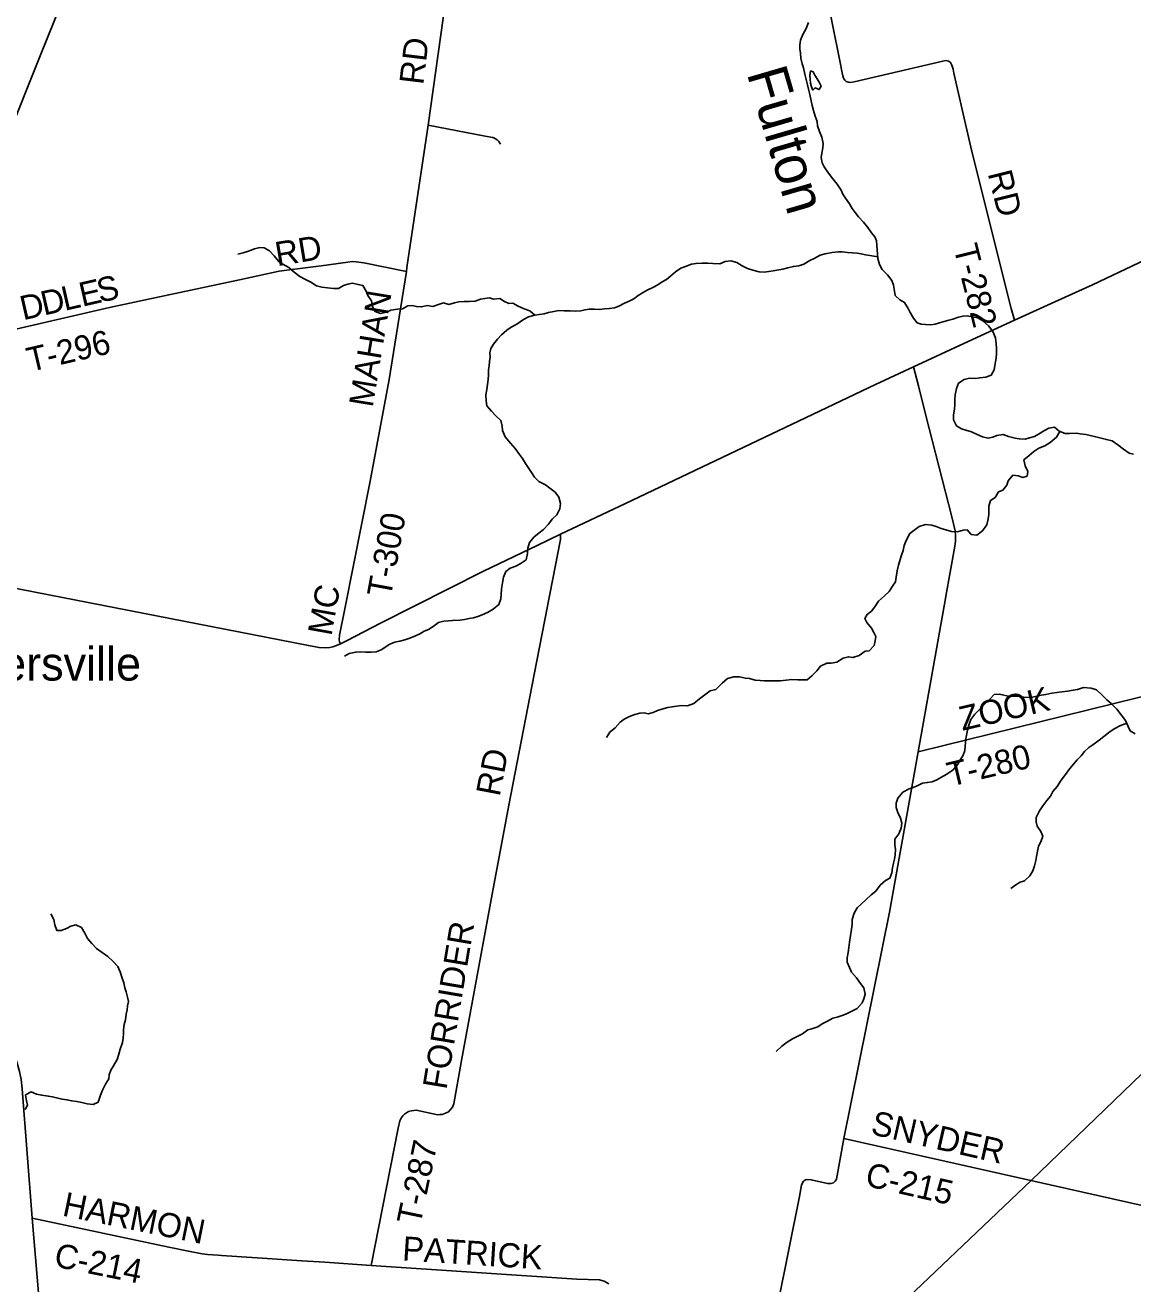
# Model space of a CAD drawing. Extents: x 0 to 34, y 0 to 22.
# Drawn here: x 6.445 to 7.746, y 17.405 to 18.883 of the extents above; entities that cross this region are included whole.
import ezdxf

# ---------------------------------------------------------------- set-up
doc = ezdxf.new("R2010")
doc.units = 0
for name, color, linetype in [('GM_X_County_Road', 7, 'Continuous'), ('GM_X_County_Road_Text', 7, 'Continuous'), ('GM_X_Minor_Lake', 7, 'Continuous'), ('GM_X_Minor_River', 7, 'Continuous'), ('GM_X_Minor_River_Text', 7, 'Continuous'), ('GM_X_Rail_Line', 7, 'Continuous'), ('GM_X_State_Route', 7, 'Continuous'), ('GM_X_Township_Road', 7, 'Continuous'), ('GM_X_Township_Road_Text', 7, 'Continuous'), ('GM_X_Unincorporated_Text', 7, 'Continuous')]:
    doc.layers.add(name, color=color, linetype=linetype)

msp = doc.modelspace()

# ---------------------------------------------------------------- linework, layer by layer
at = {"layer": 'GM_X_County_Road'}
msp.add_line((7.4066, 17.5758), (8.0124, 17.4394), dxfattribs=at)
for points in [[(6.3004, 18.376), (6.3047, 18.3928), (6.3073, 18.4041), (6.3232, 18.4893), (6.3256, 18.5003), (6.3282, 18.5101), (6.3329, 18.523), (6.3382, 18.5363), (6.4625, 18.8471), (6.5726, 19.1199), (6.732, 19.5215), (6.7919, 19.6658)], [(7.5259, 18.21), (7.5264, 18.2125), (7.5366, 18.269), (7.5376, 18.2768), (7.5377, 18.2838), (7.5373, 18.2894), (7.5333, 18.3058), (7.5028, 18.4249), (7.4943, 18.4595), (7.4881, 18.4821)], [(7.4066, 17.5758), (7.4599, 17.8414), (7.4939, 18.0298), (7.5259, 18.21)], [(7.3569, 17.5211), (7.3574, 17.523), (7.3592, 17.5255), (7.3614, 17.5271), (7.3639, 17.5277), (7.3682, 17.5273), (7.3872, 17.523), (7.3913, 17.5228), (7.3942, 17.5237), (7.3963, 17.5257), (7.3979, 17.5281), (7.4066, 17.5758)], [(7.3163, 17.3189), (7.3542, 17.5075), (7.3564, 17.5188), (7.3569, 17.5211)], [(6.4533, 17.4821), (6.6137, 17.4482), (6.6368, 17.4433), (6.6529, 17.4403), (6.6591, 17.4397), (6.6715, 17.4387), (6.6755, 17.4384)], [(6.6755, 17.4384), (6.7176, 17.4356), (6.77, 17.4322), (6.7971, 17.4304), (6.8515, 17.4267), (7.0927, 17.4107), (7.1196, 17.4096), (7.1249, 17.408), (7.1305, 17.405)]]:
    msp.add_lwpolyline(points, dxfattribs=at)
at = {"layer": 'GM_X_Minor_Lake'}
for points in [[(7.3673, 18.8296), (7.3664, 18.8241), (7.3669, 18.8198), (7.3673, 18.815), (7.3686, 18.8107), (7.3701, 18.8069), (7.3729, 18.8097), (7.3775, 18.8076), (7.3788, 18.8098)], [(7.3788, 18.8098), (7.3798, 18.8116), (7.3773, 18.8161), (7.3751, 18.8201), (7.3724, 18.8243), (7.3706, 18.8283), (7.3673, 18.8296)]]:
    msp.add_lwpolyline(points, dxfattribs=at)
at = {"layer": 'GM_X_Minor_River'}
for points in [[(7.3649, 18.8862), (7.3622, 18.8792), (7.3584, 18.8722), (7.3554, 18.8654), (7.3548, 18.8602), (7.3549, 18.8553), (7.3555, 18.8502), (7.356, 18.8445), (7.3577, 18.8378), (7.3592, 18.8329), (7.3607, 18.8255), (7.3622, 18.8194), (7.3637, 18.813), (7.365, 18.808), (7.3667, 18.8016), (7.368, 18.7945), (7.3693, 18.7889), (7.3709, 18.7828), (7.3728, 18.7765), (7.3751, 18.7699), (7.3756, 18.7649), (7.378, 18.7583), (7.3807, 18.7516), (7.382, 18.7444), (7.3819, 18.7391), (7.3808, 18.7328), (7.38, 18.7277), (7.3811, 18.7215), (7.3834, 18.7167), (7.3883, 18.7093), (7.3937, 18.7028), (7.3985, 18.6964), (7.4032, 18.6895), (7.4054, 18.6848), (7.4084, 18.68), (7.4131, 18.6733), (7.4163, 18.6678), (7.4197, 18.6631), (7.4235, 18.6583), (7.4295, 18.652), (7.4348, 18.6456), (7.4391, 18.6393), (7.4427, 18.6345), (7.4448, 18.6298), (7.4451, 18.6243), (7.4455, 18.6195), (7.4461, 18.6142), (7.4464, 18.6091), (7.4485, 18.6021), (7.4515, 18.5964), (7.4577, 18.5899), (7.463, 18.5832), (7.4649, 18.5777), (7.466, 18.5707), (7.4667, 18.5658), (7.4724, 18.5606), (7.4778, 18.5576), (7.482, 18.5503), (7.4842, 18.5456)], [(7.0434, 18.5425), (7.0375, 18.5479), (7.0309, 18.55), (7.024, 18.5531), (7.0179, 18.5567), (7.013, 18.5564), (7.0081, 18.5587), (7.0023, 18.5623), (6.9951, 18.5614), (6.9902, 18.563), (6.9847, 18.5621), (6.9796, 18.5615), (6.9733, 18.5589), (6.9667, 18.5586), (6.9607, 18.5586), (6.9542, 18.5581), (6.9493, 18.557), (6.9425, 18.5553), (6.9363, 18.5571), (6.9304, 18.555), (6.9238, 18.553), (6.917, 18.5538), (6.9105, 18.5523), (6.9045, 18.5527), (6.8994, 18.5539), (6.8943, 18.5536), (6.8882, 18.5502), (6.8822, 18.5495), (6.8746, 18.5484), (6.8695, 18.5463), (6.8623, 18.5445), (6.8559, 18.547), (6.8531, 18.5529), (6.8516, 18.5593), (6.8475, 18.5656), (6.8453, 18.5708), (6.8417, 18.5774), (6.8359, 18.5786), (6.8293, 18.5802), (6.8241, 18.5789), (6.819, 18.5774), (6.8128, 18.574), (6.8071, 18.5739), (6.7999, 18.5748), (6.7933, 18.5757), (6.7871, 18.5772), (6.7803, 18.5814), (6.7741, 18.5847), (6.7677, 18.5881), (6.7609, 18.5933), (6.7545, 18.5987), (6.7477, 18.6025), (6.7428, 18.6056), (6.7376, 18.6124), (6.732, 18.618), (6.7256, 18.6218), (6.7206, 18.6222), (6.7142, 18.6205), (6.7074, 18.6176), (6.7009, 18.6157), (6.6947, 18.6144)], [(7.4463, 18.6111), (7.4371, 18.6127), (7.432, 18.6135), (7.4269, 18.6145), (7.422, 18.6153), (7.4165, 18.6159), (7.4108, 18.6163), (7.4046, 18.6169), (7.3998, 18.6169), (7.3928, 18.6163), (7.3847, 18.6148), (7.3786, 18.6132), (7.3718, 18.6092), (7.3665, 18.6068), (7.3596, 18.6024), (7.3536, 18.6007), (7.3473, 18.5998), (7.3405, 18.5981), (7.3348, 18.5968), (7.33, 18.5959), (7.3236, 18.5948), (7.3185, 18.5941), (7.3128, 18.5933), (7.3069, 18.5934), (7.2997, 18.5955), (7.2935, 18.5974), (7.2871, 18.6006), (7.2806, 18.6045), (7.2736, 18.6064), (7.2672, 18.6055), (7.2609, 18.6031)], [(7.2609, 18.6031), (7.2527, 18.6032), (7.2469, 18.6036), (7.2399, 18.6036), (7.2329, 18.6035), (7.2274, 18.6024), (7.2204, 18.5996), (7.2151, 18.5977), (7.2086, 18.5936), (7.2031, 18.5887), (7.198, 18.5846), (7.1931, 18.5817), (7.1881, 18.5784), (7.1828, 18.5755), (7.1753, 18.5718), (7.1701, 18.5688), (7.165, 18.5658), (7.1597, 18.5617), (7.1544, 18.5589), (7.1487, 18.5566), (7.1421, 18.5533), (7.1371, 18.5514), (7.1313, 18.5505), (7.1252, 18.55), (7.1197, 18.5494), (7.1137, 18.5498), (7.1075, 18.5495), (7.1025, 18.549), (7.0974, 18.5479), (7.0908, 18.5475), (7.0848, 18.5476), (7.0782, 18.5476), (7.0719, 18.548), (7.0657, 18.5469), (7.0598, 18.5456), (7.0547, 18.5443), (7.0487, 18.5436), (7.0435, 18.5425), (7.0362, 18.5405), (7.0301, 18.5375), (7.0223, 18.5322), (7.0157, 18.5287), (7.0107, 18.5251), (7.0043, 18.5197), (6.9999, 18.5144), (6.995, 18.5085), (6.9919, 18.5036), (6.9909, 18.4985), (6.9911, 18.4938), (6.9905, 18.4883), (6.9901, 18.4831), (6.9893, 18.4784), (6.9891, 18.472), (6.9887, 18.467), (6.9881, 18.4612), (6.9871, 18.4555), (6.9859, 18.449), (6.9863, 18.4422), (6.9872, 18.4361), (6.9926, 18.43), (6.9975, 18.4247), (7.0037, 18.419), (7.005, 18.4121), (7.0055, 18.407), (7.0089, 18.3998), (7.0151, 18.3925), (7.0203, 18.3861), (7.0254, 18.3792), (7.0289, 18.3742), (7.0325, 18.3683), (7.0357, 18.3636), (7.0398, 18.3579), (7.043, 18.3523), (7.0482, 18.3472), (7.0562, 18.3432), (7.0611, 18.3395), (7.0674, 18.3347), (7.0719, 18.3288), (7.0738, 18.3216), (7.073, 18.3152), (7.0692, 18.3082), (7.064, 18.3031), (7.0597, 18.2972), (7.0538, 18.2908), (7.0488, 18.2871), (7.0422, 18.2818), (7.0374, 18.2756), (7.0355, 18.2692), (7.0351, 18.2627), (7.0333, 18.2555), (7.0265, 18.2506), (7.0212, 18.2478), (7.0144, 18.2454), (7.0096, 18.2416), (7.0069, 18.2348), (7.0056, 18.2284), (7.0046, 18.2214), (7.0042, 18.2146), (7.0038, 18.2094), (7.0013, 18.2028), (6.9946, 18.1974)], [(7.4842, 18.5456), (7.4884, 18.5391), (7.4925, 18.5336), (7.4974, 18.5319), (7.5024, 18.5315), (7.5088, 18.5313), (7.5139, 18.532), (7.5189, 18.5335), (7.5244, 18.5352), (7.5297, 18.5369), (7.5346, 18.538), (7.541, 18.5402), (7.5465, 18.5415), (7.5513, 18.5419), (7.5575, 18.5407), (7.5638, 18.5394), (7.5698, 18.5361), (7.5764, 18.53), (7.5815, 18.5236), (7.5845, 18.516), (7.5853, 18.5091), (7.5856, 18.504), (7.5856, 18.4981), (7.5854, 18.4922), (7.5838, 18.4837), (7.583, 18.4784), (7.5796, 18.4722), (7.5732, 18.4697), (7.5661, 18.4692), (7.5612, 18.4683), (7.5542, 18.4688), (7.5478, 18.467), (7.5413, 18.4628), (7.5386, 18.4566), (7.5373, 18.449), (7.5369, 18.4435), (7.5368, 18.4372), (7.5365, 18.4325), (7.5351, 18.4251), (7.5351, 18.4198), (7.5386, 18.4126), (7.5445, 18.4091), (7.5498, 18.4074), (7.5564, 18.4055), (7.5632, 18.4026), (7.5693, 18.3996), (7.5759, 18.398), (7.5814, 18.3995), (7.5861, 18.4012), (7.5934, 18.4025), (7.6, 18.4), (7.6075, 18.3981), (7.6125, 18.3975), (7.6195, 18.3969), (7.6244, 18.3984), (7.6303, 18.4002), (7.6352, 18.4027), (7.6421, 18.407), (7.6472, 18.4099), (7.654, 18.4112), (7.6593, 18.4066), (7.6665, 18.4035), (7.6714, 18.4037), (7.6792, 18.404), (7.6841, 18.4031), (7.6905, 18.4023), (7.6956, 18.4013), (7.7023, 18.3996), (7.7087, 18.398), (7.7149, 18.3965), (7.7216, 18.3949), (7.7284, 18.3905), (7.735, 18.3852), (7.7414, 18.3806), (7.7465, 18.3793)], [(7.6602, 18.4062), (7.6562, 18.3994), (7.6488, 18.3932), (7.6424, 18.3892), (7.6353, 18.3866), (7.6296, 18.3824), (7.6241, 18.3777), (7.618, 18.3726), (7.6193, 18.3658), (7.6227, 18.3589), (7.6216, 18.3536), (7.6166, 18.3521), (7.6113, 18.354), (7.6051, 18.3548), (7.5996, 18.348), (7.5979, 18.3431), (7.5933, 18.3371), (7.5882, 18.335), (7.5842, 18.3287), (7.5788, 18.3248), (7.5767, 18.3185), (7.5767, 18.3081), (7.5757, 18.3015), (7.5746, 18.2963), (7.5692, 18.2894), (7.5628, 18.2843), (7.5561, 18.285), (7.5514, 18.2904), (7.5465, 18.2902), (7.5399, 18.2881), (7.533, 18.2884), (7.5264, 18.2905), (7.5209, 18.292), (7.5149, 18.2945), (7.51, 18.2959), (7.5024, 18.2968), (7.495, 18.2944), (7.4887, 18.2897), (7.484, 18.2863), (7.4798, 18.2782), (7.4775, 18.2723), (7.4763, 18.2662), (7.4742, 18.2609), (7.4727, 18.2558), (7.4706, 18.2492), (7.469, 18.2425), (7.4678, 18.2348), (7.4671, 18.2296), (7.4636, 18.2244), (7.4596, 18.2181), (7.4541, 18.213), (7.4473, 18.2066), (7.4427, 18.2002), (7.4389, 18.1949), (7.4338, 18.1913), (7.4313, 18.1864), (7.4333, 18.1816), (7.439, 18.1749), (7.4418, 18.17), (7.4441, 18.1653), (7.4433, 18.1603), (7.442, 18.1546), (7.4364, 18.1486), (7.4317, 18.1482), (7.4245, 18.1431), (7.4169, 18.1405), (7.412, 18.1415), (7.4057, 18.1398), (7.3983, 18.1351), (7.3915, 18.134), (7.3864, 18.134), (7.379, 18.1306), (7.3746, 18.125), (7.3687, 18.1191), (7.3634, 18.1142), (7.3524, 18.1142), (7.3454, 18.1146), (7.3386, 18.1141), (7.3315, 18.1134), (7.3132, 18.1134), (7.3082, 18.1137), (7.3024, 18.1141), (7.2957, 18.116), (7.2908, 18.1162), (7.284, 18.1179), (7.2772, 18.118), (7.2698, 18.1159), (7.2635, 18.1104), (7.256, 18.1031)], [(6.9946, 18.1974), (6.988, 18.1936), (6.9817, 18.1906), (6.9768, 18.1886), (6.9715, 18.1871), (6.9666, 18.1866), (6.9609, 18.1851), (6.9554, 18.1845), (6.9469, 18.184), (6.942, 18.1835), (6.9367, 18.1832), (6.9305, 18.1819), (6.924, 18.1772), (6.9187, 18.1734), (6.9136, 18.1716), (6.9085, 18.1684), (6.9033, 18.1661), (6.8969, 18.1633), (6.891, 18.1615), (6.885, 18.1598), (6.8791, 18.1585), (6.8732, 18.1561), (6.863, 18.1497), (6.8573, 18.1473), (6.8514, 18.1467), (6.8446, 18.147), (6.8388, 18.1474), (6.8333, 18.1469), (6.8255, 18.1454), (6.82, 18.142)], [(7.256, 18.1031), (7.2494, 18.1013), (7.2431, 18.0969), (7.237, 18.0921), (7.2302, 18.0866), (7.223, 18.084), (7.216, 18.0842), (7.2047, 18.0828), (7.1998, 18.0819), (7.1926, 18.08), (7.1876, 18.0783), (7.1825, 18.0759), (7.1768, 18.0746), (7.1719, 18.0756), (7.167, 18.0753), (7.161, 18.0738), (7.1549, 18.0715), (7.1486, 18.0682), (7.1437, 18.0646), (7.1378, 18.0582), (7.1317, 18.0531), (7.1279, 18.0465)], [(7.7486, 18.0508), (7.7429, 18.0544), (7.7405, 18.0595), (7.7371, 18.0667), (7.7322, 18.0732), (7.7269, 18.0801), (7.7203, 18.0867), (7.7154, 18.0909), (7.7096, 18.0968), (7.7032, 18.1025), (7.6969, 18.1046), (7.6878, 18.1053), (7.681, 18.1032), (7.6759, 18.1021), (7.6691, 18.1012), (7.6626, 18.1004), (7.6566, 18.0997), (7.6509, 18.0988), (7.6437, 18.0973), (7.6384, 18.0965), (7.6332, 18.0952), (7.6279, 18.0939), (7.6202, 18.0938), (7.6128, 18.0948), (7.6063, 18.0952), (7.6014, 18.095), (7.5942, 18.0965), (7.5891, 18.0977), (7.5832, 18.097), (7.5779, 18.0915), (7.573, 18.0868), (7.5602, 18.0741), (7.5558, 18.0679), (7.5533, 18.061), (7.5518, 18.0552), (7.5505, 18.0493)], [(7.7387, 18.0634), (7.7305, 18.0605), (7.7246, 18.0573), (7.7191, 18.0539), (7.7118, 18.0477), (7.7063, 18.0437), (7.6989, 18.0381), (7.6942, 18.0349), (7.689, 18.0301), (7.6852, 18.0252), (7.6805, 18.0203), (7.6761, 18.0154), (7.6719, 18.0101), (7.6666, 18.0031), (7.6616, 17.9965), (7.6571, 17.9893), (7.6521, 17.9831), (7.6491, 17.9778), (7.6447, 17.9727), (7.6403, 17.9664), (7.6363, 17.9604), (7.6325, 17.9526), (7.6325, 17.9475), (7.6336, 17.9424), (7.6377, 17.9361), (7.64, 17.9308), (7.6379, 17.9241), (7.6352, 17.9192), (7.6338, 17.9131), (7.6329, 17.9069), (7.6319, 17.9022), (7.6305, 17.8959), (7.6286, 17.89), (7.625, 17.8844), (7.6185, 17.8783), (7.6136, 17.8766), (7.6085, 17.8738), (7.6024, 17.8695)], [(7.5505, 18.0493), (7.5497, 18.0446), (7.5489, 18.0364), (7.5485, 18.0315), (7.5468, 18.0258), (7.5435, 18.0207), (7.5403, 18.0152), (7.5348, 18.0088), (7.5275, 18.0037), (7.5205, 17.9995), (7.5158, 17.9969), (7.5101, 17.9947), (7.5044, 17.9937), (7.4989, 17.9932), (7.4926, 17.9898), (7.4879, 17.9881), (7.483, 17.9862), (7.4759, 17.9823), (7.4697, 17.9753), (7.4679, 17.9696), (7.4681, 17.9645), (7.4698, 17.9584), (7.4732, 17.9521), (7.4747, 17.9459), (7.4737, 17.94), (7.4712, 17.9337), (7.4664, 17.9271), (7.4662, 17.9205), (7.4671, 17.915), (7.4667, 17.9089), (7.466, 17.9038), (7.4648, 17.8991), (7.4638, 17.8937), (7.4629, 17.8877), (7.4604, 17.8814), (7.4554, 17.8786), (7.4492, 17.8733), (7.444, 17.8661), (7.4385, 17.862), (7.4271, 17.8514), (7.4222, 17.8465), (7.4185, 17.8405), (7.4164, 17.8329), (7.4162, 17.827), (7.4149, 17.819), (7.4141, 17.8143), (7.4133, 17.8065), (7.4123, 17.7999), (7.4115, 17.794), (7.4104, 17.7879), (7.4105, 17.783), (7.413, 17.7766), (7.4154, 17.7712), (7.4213, 17.7644), (7.426, 17.7579), (7.4301, 17.7526), (7.4314, 17.7452), (7.4301, 17.7399), (7.4278, 17.735), (7.4221, 17.7283), (7.4168, 17.7255), (7.4095, 17.7223), (7.4044, 17.7201), (7.3985, 17.7184), (7.3934, 17.7169), (7.3866, 17.7133), (7.3811, 17.7105), (7.3758, 17.7069), (7.3689, 17.7045), (7.3642, 17.7035), (7.3579, 17.6988), (7.3524, 17.696), (7.3462, 17.6928), (7.3399, 17.6887), (7.3336, 17.6841), (7.3268, 17.6781)], [(6.4449, 17.6098), (6.4478, 17.6149), (6.4467, 17.6198), (6.4454, 17.6269), (6.4519, 17.6304), (6.4581, 17.6279), (6.4645, 17.6265), (6.4721, 17.6255), (6.4772, 17.6246), (6.4834, 17.6232), (6.4883, 17.6218), (6.494, 17.6212), (6.4996, 17.6199), (6.5055, 17.6191), (6.5117, 17.6179), (6.5177, 17.6165), (6.5249, 17.6155), (6.5306, 17.6183), (6.5333, 17.6265), (6.536, 17.6325), (6.5394, 17.6397), (6.5431, 17.6457), (6.5438, 17.6507), (6.5456, 17.6558), (6.5486, 17.6611), (6.553, 17.6684), (6.5549, 17.6749), (6.5565, 17.6807), (6.5594, 17.6885), (6.5602, 17.6934), (6.5606, 17.6989), (6.5604, 17.7036), (6.5612, 17.7095), (6.5627, 17.7152), (6.5637, 17.7216), (6.5647, 17.7268), (6.5653, 17.7317), (6.5665, 17.7368), (6.5652, 17.7419), (6.5637, 17.7478), (6.5622, 17.7526), (6.5607, 17.7586), (6.5585, 17.7651), (6.5567, 17.7716), (6.5537, 17.7776), (6.5484, 17.7837), (6.542, 17.7893), (6.5288, 17.7987), (6.5232, 17.8048), (6.5183, 17.8105), (6.5152, 17.817), (6.511, 17.8236), (6.5046, 17.8267), (6.4986, 17.825), (6.4935, 17.8224), (6.4872, 17.82), (6.4821, 17.8202), (6.4799, 17.8267), (6.4786, 17.8331), (6.475, 17.8394)]]:
    msp.add_lwpolyline(points, dxfattribs=at)
at = {"layer": 'GM_X_Rail_Line'}
msp.add_lwpolyline([(5.2658, 15.2105), (5.3357, 15.2914), (5.4094, 15.3777), (5.4899, 15.4707), (5.6406, 15.6155), (5.8342, 15.8017), (6.1881, 16.1426), (6.4582, 16.4022), (6.7352, 16.6681), (7.0136, 16.9364), (7.2435, 17.1561), (7.4421, 17.3509), (7.6263, 17.5265), (7.9296, 17.8183), (8.0773, 17.9623), (8.4366, 18.3089), (8.7009, 18.5622), (8.9, 18.7553)], dxfattribs=at)
at = {"layer": 'GM_X_State_Route'}
for points in [[(7.6544, 18.5581), (7.6984, 18.5781), (7.7531, 18.6039), (7.8091, 18.6312), (7.8668, 18.6586), (7.9758, 18.7116), (8.2503, 18.8438), (8.5634, 18.9953), (8.5774, 19.0021), (8.5832, 19.0045), (8.5881, 19.0061), (8.5979, 19.0076), (8.6135, 19.0091), (8.9, 19.038)], [(7.5475, 18.5094), (7.6069, 18.5366), (7.6544, 18.5581)], [(7.1501, 18.3214), (7.4436, 18.4614), (7.4881, 18.4821), (7.5475, 18.5094)], [(6.2779, 18.2523), (6.7776, 18.1546), (6.7902, 18.1523), (6.7973, 18.1518), (6.8028, 18.1524), (6.8065, 18.1531), (6.8105, 18.1546), (6.8153, 18.1568), (6.8232, 18.1604), (6.8624, 18.1808), (6.9431, 18.2216), (6.9831, 18.242), (7.0462, 18.2721), (7.0738, 18.2853), (7.1501, 18.3214)], [(6.493, 17.1792), (6.4834, 17.2222), (6.4761, 17.2552), (6.4722, 17.2734), (6.47, 17.2871), (6.4683, 17.302), (6.4533, 17.4821), (6.4414, 17.6341), (6.4402, 17.6452), (6.4384, 17.6546), (6.4354, 17.6644), (6.4276, 17.6869), (6.4176, 17.7158), (6.4109, 17.7349), (6.4049, 17.7506), (6.2907, 18.0162), (6.2726, 18.0581), (6.263, 18.0811), (6.2592, 18.0916), (6.2574, 18.0987), (6.2563, 18.1035), (6.2552, 18.1144)]]:
    msp.add_lwpolyline(points, dxfattribs=at)
at = {"layer": 'GM_X_Township_Road'}
msp.add_line((7.4939, 18.0298), (7.8597, 18.12), dxfattribs=at)
for points in [[(6.8934, 18.5988), (6.9181, 18.7659), (6.9358, 18.8916), (6.9414, 18.9341), (6.951, 19.0197), (6.9543, 19.0478), (6.9557, 19.0592), (6.9568, 19.0684), (6.9602, 19.0866), (6.9719, 19.1509), (6.9917, 19.2576), (7.0211, 19.4239)], [(7.6069, 18.5366), (7.6029, 18.5504), (7.5568, 18.7347), (7.5509, 18.7604), (7.5355, 18.8269), (7.5347, 18.8314), (7.5334, 18.8364), (7.5319, 18.8392), (7.5308, 18.8403), (7.5294, 18.841), (7.5264, 18.8416), (7.5227, 18.8411), (7.4185, 18.8165), (7.4142, 18.8158), (7.412, 18.8161), (7.4092, 18.8172), (7.4075, 18.8185), (7.4062, 18.8209), (7.4053, 18.8236), (7.4046, 18.8273), (7.4019, 18.8413), (7.3578, 19.0589)], [(6.9181, 18.7659), (6.9852, 18.753), (6.9943, 18.7511)], [(6.9943, 18.7511), (6.9955, 18.7509), (6.9994, 18.7487), (7.0012, 18.7465), (7.0032, 18.7436)], [(6.3382, 18.5363), (6.4088, 18.5244), (6.4149, 18.5237), (6.4217, 18.5239), (6.4339, 18.5262), (6.5441, 18.5515), (6.6136, 18.5666), (6.6966, 18.5842), (6.7433, 18.5942), (6.7521, 18.5956), (6.7926, 18.6007), (6.8238, 18.605), (6.8289, 18.6055), (6.8336, 18.6054), (6.8426, 18.6039), (6.8927, 18.5941)], [(6.8153, 18.1568), (6.8143, 18.159), (6.8137, 18.1614), (6.8142, 18.1668), (6.8207, 18.1997), (6.85, 18.3477), (6.8724, 18.467), (6.8927, 18.5941), (6.8934, 18.5988)], [(6.9321, 17.6038), (6.9347, 17.6039), (6.9388, 17.6053), (6.942, 17.6072), (6.9447, 17.6097), (6.9469, 17.6127), (6.9484, 17.6165), (6.9576, 17.6674), (6.9704, 17.7374), (6.9935, 17.8628), (7.0131, 17.9673), (7.0426, 18.1208), (7.0737, 18.279), (7.0738, 18.2853)], [(6.889, 17.6028), (6.8903, 17.6042), (6.895, 17.6074), (6.8989, 17.6084), (6.9042, 17.6089), (6.9296, 17.6037), (6.9321, 17.6038)], [(6.8515, 17.4267), (6.8831, 17.5878), (6.885, 17.5965), (6.8869, 17.6003), (6.889, 17.6028)]]:
    msp.add_lwpolyline(points, dxfattribs=at)

# ---------------------------------------------------------------- texts
at = {"layer": 'GM_X_County_Road_Text'}
for s, rotation, p in [('SNYDER', 347.1344, (7.4369, 17.5811)), ('C-215', 347.2319, (7.4302, 17.5204)), ('HARMON', 348.5088, (6.4875, 17.4853)), ('PATRICK', 356.3036, (6.8873, 17.4326)), ('C-214', 348.6361, (6.4777, 17.4256))]:
    msp.add_text(s, height=0.02841, rotation=rotation, dxfattribs=at).set_placement(p)
at = {"layer": 'GM_X_Minor_River_Text'}
msp.add_text('Fulton', height=0.04735, rotation=286.2739, dxfattribs=at).set_placement((7.2922, 18.8269))
at = {"layer": 'GM_X_Township_Road_Text'}
for s, height, rotation, p in [('RD', 0.02841, 83.0591, (6.9125, 18.8124)), ('RD', 0.02841, 284.0363, (7.5753, 18.7092)), ('RD', 0.02841, 9.38, (6.741, 18.6)), ('T-282', 0.02841, 284.1723, (7.535, 18.6223)), ('E', 0.0284, 12.8928, (6.512, 18.5524)), ('S', 0.0284, 12.8942, (6.5327, 18.5571)), ('D', 0.0284, 12.8876, (6.4426, 18.5365)), ('D', 0.0284, 12.8928, (6.467, 18.5421)), ('L', 0.0284, 12.8928, (6.4913, 18.5476)), ('MAHAN', 0.02841, 80.6266, (6.8531, 18.4335)), ('T-296', 0.02841, 13.0162, (6.4506, 18.4759)), ('T-300', 0.02841, 79.5701, (6.8742, 18.21)), ('MC', 0.02841, 79.8138, (6.8047, 18.1651)), ('ZOOK', 0.02841, 13.2551, (7.5456, 18.0544)), ('T-280', 0.02841, 13.2888, (7.5316, 17.9889)), ('RD', 0.02841, 79.0777, (7.0022, 17.9765)), ('FORRIDER', 0.02841, 80.4469, (6.9397, 17.6323)), ('T-287', 0.02841, 78.1401, (6.909, 17.473))]:
    msp.add_text(s, height=height, rotation=rotation, dxfattribs=at).set_placement(p)
at = {"layer": 'GM_X_Unincorporated_Text'}
msp.add_text('Somersville', height=0.039489, rotation=0, dxfattribs=at).set_placement((6.3082, 18.1135))

doc.saveas('drawing.dxf')
